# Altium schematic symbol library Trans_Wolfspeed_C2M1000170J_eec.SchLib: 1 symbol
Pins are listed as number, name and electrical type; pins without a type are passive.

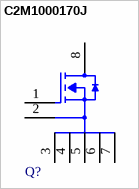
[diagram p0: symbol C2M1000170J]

## C2M1000170J
designator Q?  (value not drawn)
pins: 1 Gate, 2 Driver Source, 3 Power Source, 4 Power Source, 5 Power Source, 6 Power Source, 7 Power Source, 8 Drain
